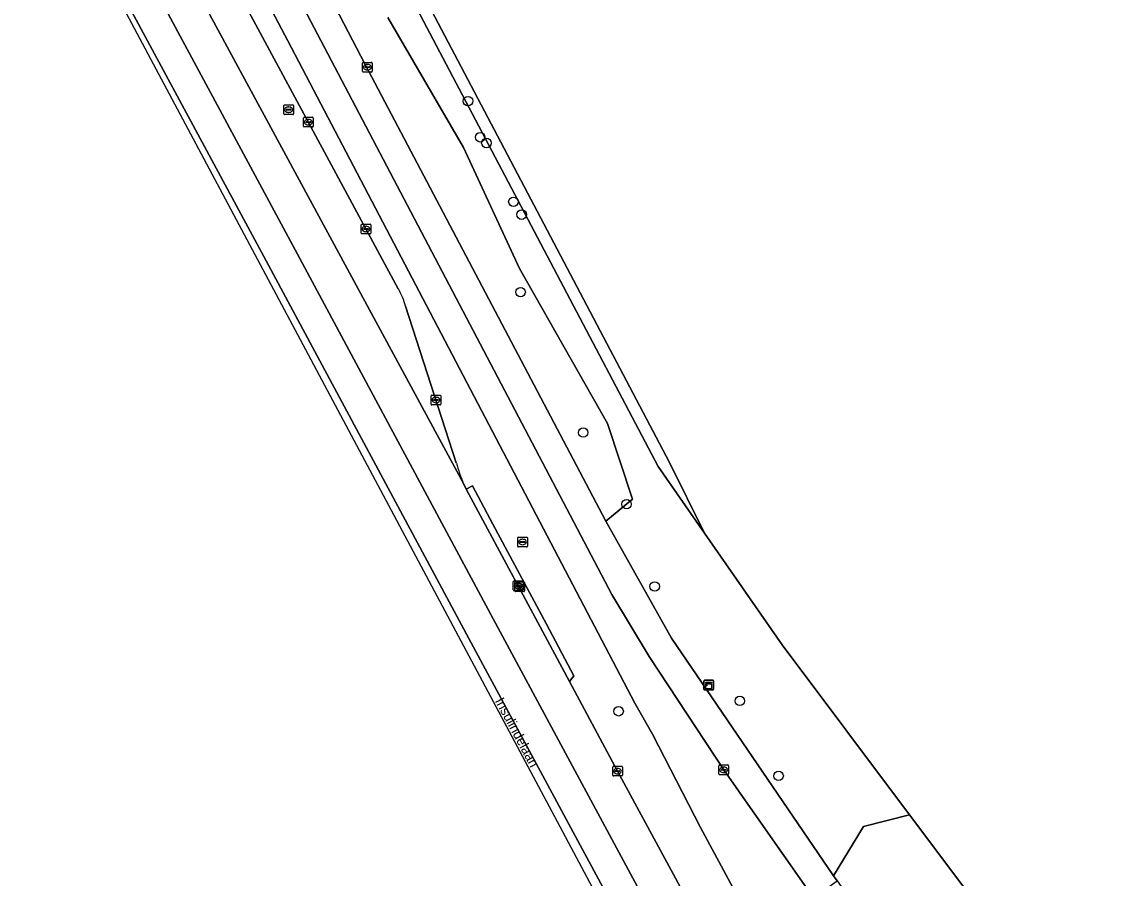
# Model space of a CAD drawing. Extents: x 162417 to 163722, y 384268 to 385417.
# Drawn here: x 162734.5 to 162846, y 384388.4 to 384476.6 of the extents above; entities that cross this region are included whole.
import ezdxf

# ---------------------------------------------------------------- set-up
doc = ezdxf.new("R2010")
doc.units = 0
for name, color, linetype in [('IMGEO_Berm_groen', 7, 'Continuous'), ('IMGEO_Boom', 7, 'Continuous'), ('IMGEO_Fietspad_open', 7, 'Continuous'), ('IMGEO_Groenvoorziening', 7, 'Continuous'), ('IMGEO_Kast', 7, 'Continuous'), ('IMGEO_Kolk', 7, 'Continuous'), ('IMGEO_Meer_plas_ven_vijver', 7, 'Continuous'), ('IMGEO_Openbare_ruimte_label', 7, 'Continuous'), ('IMGEO_Rijbaan_regionaal_gesloten', 7, 'Continuous'), ('IMGEO_Rioolput', 7, 'Continuous'), ('IMGEO_Terreindeel_open', 7, 'Continuous'), ('IMGEO_Voetpad_open', 7, 'Continuous')]:
    doc.layers.add(name, color=color, linetype=linetype)

msp = doc.modelspace()

# ---------------------------------------------------------------- linework, layer by layer
at = {"layer": 'IMGEO_Berm_groen'}
for points in [[(162754.27, 384502.15), (162755.39, 384500), (162769.87, 384472.16), (162794.62, 384425.16), (162797.36, 384427.41), (162794.8, 384435.21), (162785.75, 384451.17), (162779.97, 384463.61), (162772.19, 384477)], [(162816.42, 384372.9), (162812.18, 384379.37), (162810.21, 384382.67), (162810.08, 384382.89), (162808.48, 384386.03), (162807.93, 384387.03), (162804.38, 384393.64), (162799.42, 384403.24), (162797.61, 384406.44), (162761.9, 384474.57), (162755.43, 384486.9), (162751.85, 384493.51), (162748.56, 384499.79)], [(162746.31, 384499.11), (162773.28, 384449.07)], [(162774.01, 384447.28), (162779.24, 384431.15)], [(162779.97, 384429.02), (162780.27, 384428.44), (162780.92, 384428.78), (162782.99, 384424.84), (162788.51, 384414.57), (162791.34, 384409.23), (162791.24, 384409.1), (162790.89, 384408.66), (162795.83, 384399.44), (162823.04, 384349.18), (162830.65, 384335.7), (162839.9, 384319.71)]]:
    msp.add_lwpolyline(points, dxfattribs=at)
for centre, radius, start, end in [((162766.73, 384445.34), 7.54, 14.8426, 29.5957), ((162795.8, 384435.6), 17.14, 195.0738, 202.5866)]:
    msp.add_arc(centre, radius, start, end, dxfattribs=at)
at = {"layer": 'IMGEO_Boom'}
for centre in [(162780.45, 384468.38), (162781.7, 384464.66), (162782.34, 384464.07), (162785.12, 384458.02), (162785.97, 384456.7), (162785.86, 384448.73), (162792.3, 384434.28), (162796.76, 384426.91), (162799.65, 384418.44), (162808.41, 384406.67), (162795.94, 384405.6), (162812.4, 384398.95)]:
    msp.add_circle(centre, 0.489, dxfattribs=at)
at = {"layer": 'IMGEO_Fietspad_open'}
msp.add_lwpolyline([(162764.98, 384475.28), (162757.93, 384488.68), (162752.8, 384498.47), (162752.11, 384500), (162748.56, 384499.79), (162751.85, 384493.51), (162755.43, 384486.9), (162761.9, 384474.57), (162797.61, 384406.44), (162799.42, 384403.24), (162804.38, 384393.64), (162807.93, 384387.03), (162808.48, 384386.03), (162810.08, 384382.89), (162810.21, 384382.67), (162813.11, 384384.55), (162816, 384386.42), (162806.83, 384399.46), (162799.07, 384411.25), (162795.23, 384417.63)], close=True, dxfattribs=at)
at = {"layer": 'IMGEO_Groenvoorziening'}
for points in [[(162767.81, 384491.93), (162800.01, 384430.78), (162804.77, 384423.92), (162801.16, 384431.19), (162768.87, 384492.59)], [(162772.19, 384477), (162779.97, 384463.61), (162785.75, 384451.17), (162794.8, 384435.21), (162797.36, 384427.41), (162794.62, 384425.16), (162801.38, 384413.11), (162818.05, 384388.68), (162821.14, 384393.75), (162825.87, 384394.96), (162812.76, 384412.45), (162804.77, 384423.92), (162800.01, 384430.78), (162767.81, 384491.93)], [(162847.62, 384365.96), (162825.87, 384394.96), (162821.14, 384393.75), (162818.05, 384388.68), (162818.43, 384388.14), (162860.16, 384329.06)]]:
    msp.add_lwpolyline(points, dxfattribs=at)
at = {"layer": 'IMGEO_Kast'}
for p, q in [((162804.72, 384407.87), (162804.72, 384408.71)), ((162804.72, 384408.71), (162804.72, 384407.87)), ((162804.79, 384408.79), (162805.63, 384408.79)), ((162805.63, 384408.79), (162804.79, 384408.79)), ((162805.71, 384408.72), (162805.71, 384407.88)), ((162805.71, 384407.88), (162805.71, 384408.72)), ((162805.64, 384407.79), (162804.8, 384407.79)), ((162804.8, 384407.79), (162805.64, 384407.79))]:
    msp.add_line(p, q, dxfattribs=at)
for points in [[(162804.91, 384408.58), (162805.51, 384408.58), (162805.51, 384408.5), (162804.91, 384408.5), (162804.91, 384408.58)], [(162804.91, 384408.41), (162805.51, 384408.41), (162805.51, 384407.92), (162804.91, 384407.92), (162804.91, 384408.41)]]:
    msp.add_lwpolyline(points, dxfattribs=at)
msp.add_circle((162804.99, 384408.26), 0.0377, dxfattribs=at)
for centre, start, end in [((162804.79, 384408.71), 92.4484, 184.2845), ((162804.79, 384408.71), 92.4484, 184.2845), ((162805.64, 384408.71), 2.4484, 94.2845), ((162805.64, 384408.71), 2.4484, 94.2845), ((162804.79, 384407.87), 182.4484, 274.2845), ((162804.79, 384407.87), 182.4484, 274.2845), ((162805.64, 384407.87), 272.4484, 4.2845), ((162805.64, 384407.87), 272.4484, 4.2845)]:
    msp.add_arc(centre, 0.0779, start, end, dxfattribs=at)
at = {"layer": 'IMGEO_Kolk'}
for p, q in [((162763.53, 384465.79), (162763.53, 384466.64)), ((162763.6, 384466.72), (162764.45, 384466.72)), ((162763.79, 384466.21), (162763.79, 384466.22)), ((162763.83, 384466.26), (162764.23, 384466.26)), ((162764.22, 384466.17), (162763.83, 384466.17)), ((162764.02, 384466.5), (162764.04, 384466.5)), ((162764.27, 384466.22), (162764.27, 384466.21)), ((162764.53, 384466.64), (162764.53, 384465.79)), ((162764.45, 384465.72), (162763.6, 384465.72)), ((162764.04, 384465.94), (162764.01, 384465.94)), ((162769.46, 384454.79), (162769.46, 384455.65)), ((162769.54, 384455.72), (162770.39, 384455.72)), ((162769.72, 384455.21), (162769.72, 384455.23)), ((162769.76, 384455.26), (162770.16, 384455.26)), ((162770.16, 384455.18), (162769.76, 384455.18)), ((162769.95, 384455.5), (162769.98, 384455.5)), ((162769.97, 384454.94), (162769.95, 384454.94)), ((162770.21, 384455.23), (162770.21, 384455.21)), ((162770.46, 384455.65), (162770.46, 384454.79)), ((162770.39, 384454.72), (162769.54, 384454.72)), ((162776.65, 384437.2), (162776.65, 384438.06)), ((162776.72, 384438.13), (162777.58, 384438.13)), ((162777.58, 384437.13), (162776.72, 384437.13)), ((162776.91, 384437.62), (162776.91, 384437.64)), ((162776.95, 384437.67), (162777.35, 384437.67)), ((162777.34, 384437.59), (162776.95, 384437.59)), ((162777.16, 384437.35), (162777.13, 384437.35)), ((162777.14, 384437.91), (162777.16, 384437.91)), ((162777.39, 384437.64), (162777.39, 384437.62)), ((162777.65, 384438.06), (162777.65, 384437.2)), ((162785.11, 384418.08), (162785.11, 384418.94)), ((162785.19, 384419.01), (162786.04, 384419.01)), ((162785.27, 384417.99), (162785.27, 384418.85)), ((162785.34, 384418.92), (162786.19, 384418.92)), ((162785.37, 384418.5), (162785.37, 384418.52)), ((162785.81, 384418.47), (162785.41, 384418.47)), ((162785.42, 384418.55), (162785.81, 384418.55)), ((162785.52, 384418.41), (162785.52, 384418.43)), ((162785.96, 384418.38), (162785.56, 384418.38)), ((162785.57, 384418.46), (162785.96, 384418.46)), ((162785.6, 384418.79), (162785.63, 384418.79)), ((162785.62, 384418.23), (162785.6, 384418.23)), ((162785.75, 384418.7), (162785.78, 384418.7)), ((162785.78, 384418.14), (162785.75, 384418.14)), ((162785.86, 384418.52), (162785.86, 384418.5)), ((162786.01, 384418.43), (162786.01, 384418.41)), ((162786.11, 384418.94), (162786.11, 384418.08)), ((162786.27, 384418.85), (162786.27, 384417.99)), ((162786.04, 384418.01), (162785.19, 384418.01)), ((162786.19, 384417.92), (162785.34, 384417.92)), ((162795.33, 384399.01), (162795.33, 384399.86)), ((162795.41, 384399.94), (162796.26, 384399.94)), ((162795.59, 384399.43), (162795.59, 384399.44)), ((162796.03, 384399.39), (162795.63, 384399.39)), ((162795.64, 384399.48), (162796.03, 384399.48)), ((162795.82, 384399.72), (162795.85, 384399.72)), ((162796.08, 384399.44), (162796.08, 384399.43)), ((162796.33, 384399.86), (162796.33, 384399.01)), ((162806.26, 384399.15), (162806.26, 384400)), ((162806.33, 384400.08), (162807.18, 384400.08)), ((162806.52, 384399.57), (162806.52, 384399.58)), ((162806.56, 384399.62), (162806.96, 384399.62)), ((162806.95, 384399.53), (162806.56, 384399.53)), ((162806.77, 384399.3), (162806.74, 384399.3)), ((162806.75, 384399.85), (162806.77, 384399.85)), ((162807, 384399.58), (162807, 384399.57)), ((162807.26, 384400), (162807.26, 384399.15)), ((162796.26, 384398.94), (162795.41, 384398.94)), ((162795.84, 384399.16), (162795.82, 384399.16)), ((162807.18, 384399.07), (162806.33, 384399.07))]:
    msp.add_line(p, q, dxfattribs=at)
for points in [[(162763.53, 384465.79), (162763.53, 384466.64)], [(162763.6, 384466.72), (162764.45, 384466.72)], [(162764.53, 384466.64), (162764.53, 384465.79)], [(162764.45, 384465.72), (162763.6, 384465.72)], [(162769.46, 384454.79), (162769.46, 384455.65)], [(162769.54, 384455.72), (162770.39, 384455.72)], [(162770.46, 384455.65), (162770.46, 384454.79)], [(162770.39, 384454.72), (162769.54, 384454.72)], [(162776.65, 384437.2), (162776.65, 384438.06)], [(162776.72, 384438.13), (162777.58, 384438.13)], [(162777.58, 384437.13), (162776.72, 384437.13)], [(162777.65, 384438.06), (162777.65, 384437.2)], [(162785.11, 384418.08), (162785.11, 384418.94)], [(162785.19, 384419.01), (162786.04, 384419.01)], [(162785.27, 384417.99), (162785.27, 384418.85)], [(162785.34, 384418.92), (162786.19, 384418.92)], [(162786.11, 384418.94), (162786.11, 384418.08)], [(162786.27, 384418.85), (162786.27, 384417.99)], [(162786.04, 384418.01), (162785.19, 384418.01)], [(162786.19, 384417.92), (162785.34, 384417.92)], [(162795.33, 384399.01), (162795.33, 384399.86)], [(162795.41, 384399.94), (162796.26, 384399.94)], [(162796.33, 384399.86), (162796.33, 384399.01)], [(162806.26, 384399.15), (162806.26, 384400)], [(162806.33, 384400.08), (162807.18, 384400.08)], [(162807.26, 384400), (162807.26, 384399.15)], [(162796.26, 384398.94), (162795.41, 384398.94)], [(162807.18, 384399.07), (162806.33, 384399.07)]]:
    msp.add_lwpolyline(points, dxfattribs=at)
for centre, radius, start, end in [((162763.6, 384466.64), 0.0765, 91.552, 178.448), ((162763.6, 384466.64), 0.0765, 91.552, 178.448), ((162763.83, 384466.22), 0.0403, 85.8775, 175.7526), ((162763.82, 384466.21), 0.0366, 178.938, 274.7102), ((162764.23, 384466.22), 0.043, 264.8664, 352.4533), ((162764.23, 384466.22), 0.0386, 1.7309, 96.639), ((162764.45, 384466.64), 0.0765, 1.552, 88.448), ((162764.45, 384466.64), 0.0765, 1.552, 88.448), ((162763.6, 384465.79), 0.0765, 181.552, 268.448), ((162763.6, 384465.79), 0.0765, 181.552, 268.448), ((162764.45, 384465.79), 0.0765, 271.552, 358.448), ((162764.45, 384465.79), 0.0765, 271.552, 358.448), ((162769.54, 384455.64), 0.0765, 91.552, 178.448), ((162769.54, 384455.64), 0.0765, 91.552, 178.448), ((162769.76, 384455.22), 0.0403, 85.8775, 175.7526), ((162769.76, 384455.21), 0.0366, 178.938, 274.7102), ((162770.17, 384455.22), 0.0386, 1.7309, 96.639), ((162770.16, 384455.22), 0.043, 264.8664, 352.4533), ((162770.39, 384455.64), 0.0765, 1.552, 88.448), ((162770.39, 384455.64), 0.0765, 1.552, 88.448), ((162769.54, 384454.8), 0.0765, 181.552, 268.448), ((162769.54, 384454.8), 0.0765, 181.552, 268.448), ((162770.39, 384454.8), 0.0765, 271.552, 358.448), ((162770.39, 384454.8), 0.0765, 271.552, 358.448), ((162776.72, 384438.05), 0.0765, 91.552, 178.448), ((162776.72, 384438.05), 0.0765, 91.552, 178.448), ((162776.72, 384437.2), 0.0765, 181.552, 268.448), ((162776.72, 384437.2), 0.0765, 181.552, 268.448), ((162776.95, 384437.63), 0.0403, 85.8775, 175.7526), ((162776.94, 384437.62), 0.0366, 178.938, 274.7102), ((162777.35, 384437.63), 0.043, 264.8664, 352.4533), ((162777.35, 384437.63), 0.0386, 1.7309, 96.639), ((162777.57, 384438.05), 0.0765, 1.552, 88.448), ((162777.57, 384438.05), 0.0765, 1.552, 88.448), ((162777.57, 384437.2), 0.0765, 271.552, 358.448), ((162777.57, 384437.2), 0.0765, 271.552, 358.448), ((162785.19, 384418.93), 0.0765, 91.552, 178.448), ((162785.19, 384418.93), 0.0765, 91.552, 178.448), ((162785.34, 384418.84), 0.0765, 91.552, 178.448), ((162785.34, 384418.84), 0.0765, 91.552, 178.448), ((162785.41, 384418.51), 0.0403, 85.8775, 175.7526), ((162785.41, 384418.5), 0.0366, 178.938, 274.7102), ((162785.56, 384418.42), 0.0403, 85.8775, 175.7526), ((162785.56, 384418.41), 0.0366, 178.938, 274.7102), ((162785.82, 384418.51), 0.0386, 1.7309, 96.639), ((162785.81, 384418.51), 0.043, 264.8664, 352.4533), ((162785.97, 384418.42), 0.0386, 1.7309, 96.639), ((162785.97, 384418.42), 0.043, 264.8664, 352.4533), ((162786.04, 384418.93), 0.0765, 1.552, 88.448), ((162786.04, 384418.93), 0.0765, 1.552, 88.448), ((162786.19, 384418.84), 0.0765, 1.552, 88.448), ((162786.19, 384418.84), 0.0765, 1.552, 88.448), ((162785.19, 384418.09), 0.0765, 181.552, 268.448), ((162785.19, 384418.09), 0.0765, 181.552, 268.448), ((162785.34, 384417.99), 0.0765, 181.552, 268.448), ((162785.34, 384417.99), 0.0765, 181.552, 268.448), ((162786.04, 384418.09), 0.0765, 271.552, 358.448), ((162786.04, 384418.09), 0.0765, 271.552, 358.448), ((162786.19, 384417.99), 0.0765, 271.552, 358.448), ((162786.19, 384417.99), 0.0765, 271.552, 358.448), ((162795.41, 384399.86), 0.0765, 91.552, 178.448), ((162795.41, 384399.86), 0.0765, 91.552, 178.448), ((162795.63, 384399.44), 0.0403, 85.8775, 175.7526), ((162795.63, 384399.43), 0.0366, 178.938, 274.7102), ((162796.04, 384399.44), 0.0386, 1.7309, 96.639), ((162796.03, 384399.44), 0.043, 264.8664, 352.4533), ((162796.26, 384399.86), 0.0765, 1.552, 88.448), ((162796.26, 384399.86), 0.0765, 1.552, 88.448), ((162806.33, 384400), 0.0765, 91.552, 178.448), ((162806.33, 384400), 0.0765, 91.552, 178.448), ((162806.56, 384399.58), 0.0403, 85.8775, 175.7526), ((162806.55, 384399.57), 0.0366, 178.938, 274.7102), ((162806.96, 384399.57), 0.043, 264.8664, 352.4533), ((162806.96, 384399.58), 0.0386, 1.7309, 96.639), ((162807.18, 384400), 0.0765, 1.552, 88.448), ((162807.18, 384400), 0.0765, 1.552, 88.448), ((162795.41, 384399.01), 0.0765, 181.552, 268.448), ((162795.41, 384399.01), 0.0765, 181.552, 268.448), ((162796.26, 384399.01), 0.0765, 271.552, 358.448), ((162796.26, 384399.01), 0.0765, 271.552, 358.448), ((162806.33, 384399.15), 0.0765, 181.552, 268.448), ((162806.33, 384399.15), 0.0765, 181.552, 268.448), ((162807.18, 384399.15), 0.0765, 271.552, 358.448), ((162807.18, 384399.15), 0.0765, 271.552, 358.448)]:
    msp.add_arc(centre, radius, start, end, dxfattribs=at)
for centre, major_axis, ratio, start_param, end_param in [((162764.01, 384466.22), (-0.387, 0.002), 0.722429, 4.712389, 7.853982), ((162764.04, 384466.22), (-0.39, 0.002), 0.717154, 1.570796, 4.712389), ((162769.95, 384455.22), (-0.387, 0.002), 0.722429, 4.712389, 7.853982), ((162769.97, 384455.22), (-0.39, 0.002), 0.717154, 1.570796, 4.712389), ((162777.14, 384437.63), (-0.387, 0.002), 0.722429, 4.712389, 7.853982), ((162777.16, 384437.63), (-0.39, 0.002), 0.717154, 1.570796, 4.712389), ((162785.6, 384418.51), (-0.387, 0.002), 0.722429, 4.712389, 7.853982), ((162785.75, 384418.42), (-0.387, 0.002), 0.722429, 4.712389, 7.853982), ((162785.62, 384418.51), (-0.39, 0.002), 0.717154, 1.570796, 4.712389), ((162785.78, 384418.42), (-0.39, 0.002), 0.717154, 1.570796, 4.712389), ((162795.82, 384399.44), (-0.387, 0.002), 0.722429, 4.712389, 7.853982), ((162795.84, 384399.44), (-0.39, 0.002), 0.717154, 1.570796, 4.712389), ((162806.74, 384399.57), (-0.387, 0.002), 0.722429, 4.712389, 7.853982), ((162806.77, 384399.57), (-0.39, 0.002), 0.717154, 1.570796, 4.712389)]:
    msp.add_ellipse(centre, major_axis=major_axis, ratio=ratio, start_param=start_param, end_param=end_param, dxfattribs=at)
at = {"layer": 'IMGEO_Meer_plas_ven_vijver'}
msp.add_lwpolyline([(162768.87, 384492.59), (162801.16, 384431.19), (162804.77, 384423.92), (162812.76, 384412.45), (162825.87, 384394.96), (162847.62, 384365.96), (162858.02, 384352.1), (162869.39, 384336.93), (162873.92, 384331.77), (162873.94, 384331.75), (162880.68, 384326.96), (162888.3, 384324.02), (162890.62, 384323.75), (162895.67, 384323.18), (162904.39, 384324.1), (162927.53, 384330.45), (162944.64, 384335.14), (162971.11, 384342.4), (162976.25, 384406.67), (162962.24, 384407.64), (162968.83, 384503.48)], dxfattribs=at)
at = {"layer": 'IMGEO_Rijbaan_regionaal_gesloten'}
for points in [[(162742.36, 384498.6), (162742.11, 384498.57), (162738.46, 384498.1), (162742.85, 384489.94), (162762.9, 384452.62), (162783.02, 384415.1), (162802.43, 384379.07), (162810.84, 384363.47), (162822.01, 384342.68), (162828.12, 384331.64), (162832.26, 384324.52), (162835.94, 384318.64), (162840.23, 384312.43), (162842.77, 384309.11), (162846.14, 384305.7), (162857.34, 384295.59), (162861.95, 384291.57), (162872.15, 384283.83)], [(162746.31, 384499.11), (162742.59, 384498.63), (162742.36, 384498.6), (162779.97, 384429.02)], [(162839.9, 384319.71), (162830.65, 384335.7), (162823.04, 384349.18), (162795.83, 384399.44), (162790.89, 384408.66), (162786.13, 384417.55), (162780.27, 384428.44), (162779.97, 384429.02), (162742.36, 384498.6)], [(162773.28, 384449.07), (162746.31, 384499.11)], [(162734.54, 384497.59), (162794.86, 384384.42), (162830.58, 384316.87), (162838.99, 384308.46), (162838.41, 384309.08), (162835.68, 384312.55), (162832.33, 384317.3), (162828.35, 384324.29), (162825.26, 384329.91), (162819.13, 384341.17), (162808.47, 384361.16), (162799.61, 384377.69), (162780.52, 384413.08), (162759.93, 384451.49), (162740.22, 384488.09), (162734.96, 384497.64), (162734.54, 384497.59)], [(162846.14, 384305.7), (162842.77, 384309.11), (162840.23, 384312.43), (162835.94, 384318.64), (162832.26, 384324.52), (162828.12, 384331.64), (162822.01, 384342.68), (162810.84, 384363.47), (162802.43, 384379.07), (162783.02, 384415.1), (162762.9, 384452.62), (162742.85, 384489.94)], [(162740.22, 384488.09), (162759.93, 384451.49), (162780.52, 384413.08), (162799.61, 384377.69), (162808.47, 384361.16), (162819.13, 384341.17), (162825.26, 384329.91), (162828.35, 384324.29), (162832.33, 384317.3), (162835.68, 384312.55), (162838.41, 384309.08), (162838.99, 384308.46), (162849.39, 384298.06)], [(162779.24, 384431.15), (162774.01, 384447.28)]]:
    msp.add_lwpolyline(points, dxfattribs=at)
for centre, radius, start, end in [((162766.73, 384445.34), 7.54, 14.8426, 29.5957), ((162795.8, 384435.6), 17.14, 195.0738, 202.5866)]:
    msp.add_arc(centre, radius, start, end, dxfattribs=at)
at = {"layer": 'IMGEO_Rioolput'}
for p, q in [((162769.59, 384471.45), (162769.59, 384472.3)), ((162769.67, 384472.37), (162770.52, 384472.37)), ((162769.85, 384471.87), (162769.85, 384471.88)), ((162770.29, 384471.83), (162769.89, 384471.83)), ((162769.9, 384471.92), (162770.29, 384471.92)), ((162770.08, 384472.15), (162770.11, 384472.15)), ((162770.34, 384471.88), (162770.34, 384471.87)), ((162770.6, 384472.3), (162770.6, 384471.45)), ((162770.52, 384471.37), (162769.67, 384471.37)), ((162770.1, 384471.59), (162770.08, 384471.59)), ((162761.5, 384467.07), (162761.5, 384467.92)), ((162761.58, 384468), (162762.43, 384468)), ((162761.76, 384467.49), (162761.76, 384467.5)), ((162762.2, 384467.45), (162761.8, 384467.45)), ((162761.81, 384467.54), (162762.2, 384467.54)), ((162761.99, 384467.78), (162762.02, 384467.78)), ((162762.01, 384467.22), (162761.99, 384467.22)), ((162762.25, 384467.5), (162762.25, 384467.49)), ((162762.51, 384467.92), (162762.51, 384467.07)), ((162762.43, 384467), (162761.58, 384467)), ((162785.56, 384422.59), (162785.56, 384423.44)), ((162785.63, 384423.52), (162786.49, 384423.52)), ((162785.82, 384423.01), (162785.82, 384423.02)), ((162785.86, 384423.06), (162786.26, 384423.06)), ((162786.25, 384422.97), (162785.86, 384422.97)), ((162786.07, 384422.74), (162786.04, 384422.74)), ((162786.05, 384423.3), (162786.07, 384423.3)), ((162786.3, 384423.02), (162786.3, 384423.01)), ((162786.56, 384423.44), (162786.56, 384422.59)), ((162786.49, 384422.52), (162785.63, 384422.52))]:
    msp.add_line(p, q, dxfattribs=at)
for points in [[(162769.59, 384471.45), (162769.59, 384472.3)], [(162769.67, 384472.37), (162770.52, 384472.37)], [(162770.6, 384472.3), (162770.6, 384471.45)], [(162770.52, 384471.37), (162769.67, 384471.37)], [(162761.5, 384467.07), (162761.5, 384467.92)], [(162761.58, 384468), (162762.43, 384468)], [(162762.51, 384467.92), (162762.51, 384467.07)], [(162762.43, 384467), (162761.58, 384467)], [(162785.56, 384422.59), (162785.56, 384423.44)], [(162785.63, 384423.52), (162786.49, 384423.52)], [(162786.56, 384423.44), (162786.56, 384422.59)], [(162786.49, 384422.52), (162785.63, 384422.52)]]:
    msp.add_lwpolyline(points, dxfattribs=at)
for centre, radius, start, end in [((162769.67, 384472.3), 0.0765, 91.552, 178.448), ((162769.67, 384472.3), 0.0765, 91.552, 178.448), ((162769.89, 384471.88), 0.0403, 85.8775, 175.7526), ((162769.89, 384471.87), 0.0366, 178.938, 274.7102), ((162770.3, 384471.88), 0.0386, 1.7309, 96.639), ((162770.29, 384471.87), 0.043, 264.8664, 352.4533), ((162770.52, 384472.3), 0.0765, 1.552, 88.448), ((162770.52, 384472.3), 0.0765, 1.552, 88.448), ((162769.67, 384471.45), 0.0765, 181.552, 268.448), ((162769.67, 384471.45), 0.0765, 181.552, 268.448), ((162770.52, 384471.45), 0.0765, 271.552, 358.448), ((162770.52, 384471.45), 0.0765, 271.552, 358.448), ((162761.58, 384467.92), 0.0765, 91.552, 178.448), ((162761.58, 384467.92), 0.0765, 91.552, 178.448), ((162761.8, 384467.5), 0.0403, 85.8775, 175.7526), ((162761.8, 384467.49), 0.0366, 178.938, 274.7102), ((162762.21, 384467.5), 0.0386, 1.7309, 96.639), ((162762.2, 384467.5), 0.043, 264.8664, 352.4533), ((162762.43, 384467.92), 0.0765, 1.552, 88.448), ((162762.43, 384467.92), 0.0765, 1.552, 88.448), ((162761.58, 384467.07), 0.0765, 181.552, 268.448), ((162761.58, 384467.07), 0.0765, 181.552, 268.448), ((162762.43, 384467.07), 0.0765, 271.552, 358.448), ((162762.43, 384467.07), 0.0765, 271.552, 358.448), ((162785.63, 384423.44), 0.0765, 91.552, 178.448), ((162785.63, 384423.44), 0.0765, 91.552, 178.448), ((162785.63, 384422.59), 0.0765, 181.552, 268.448), ((162785.63, 384422.59), 0.0765, 181.552, 268.448), ((162785.86, 384423.02), 0.0403, 85.8775, 175.7526), ((162785.85, 384423.01), 0.0366, 178.938, 274.7102), ((162786.26, 384423.02), 0.043, 264.8664, 352.4533), ((162786.26, 384423.02), 0.0386, 1.7309, 96.639), ((162786.48, 384423.44), 0.0765, 1.552, 88.448), ((162786.48, 384423.44), 0.0765, 1.552, 88.448), ((162786.48, 384422.59), 0.0765, 271.552, 358.448), ((162786.48, 384422.59), 0.0765, 271.552, 358.448)]:
    msp.add_arc(centre, radius, start, end, dxfattribs=at)
for centre, major_axis, ratio, start_param, end_param in [((162770.08, 384471.87), (-0.387, 0.002), 0.722429, 4.712389, 7.853982), ((162770.11, 384471.87), (-0.39, 0.002), 0.717154, 1.570796, 4.712389), ((162761.99, 384467.5), (-0.387, 0.002), 0.722429, 4.712389, 7.853982), ((162762.02, 384467.5), (-0.39, 0.002), 0.717154, 1.570796, 4.712389), ((162786.05, 384423.02), (-0.387, 0.002), 0.722429, 4.712389, 7.853982), ((162786.07, 384423.02), (-0.39, 0.002), 0.717154, 1.570796, 4.712389)]:
    msp.add_ellipse(centre, major_axis=major_axis, ratio=ratio, start_param=start_param, end_param=end_param, dxfattribs=at)
at = {"layer": 'IMGEO_Terreindeel_open'}
msp.add_lwpolyline([(162780.27, 384428.44), (162786.13, 384417.55), (162790.89, 384408.66), (162791.24, 384409.1), (162791.34, 384409.23), (162788.51, 384414.57), (162782.99, 384424.84), (162780.92, 384428.78)], close=True, dxfattribs=at)
at = {"layer": 'IMGEO_Voetpad_open'}
msp.add_lwpolyline([(162752.11, 384500), (162752.8, 384498.47), (162757.93, 384488.68), (162764.98, 384475.28), (162795.23, 384417.63), (162799.07, 384411.25), (162806.83, 384399.46), (162816, 384386.42), (162818.43, 384388.14), (162818.05, 384388.68), (162801.38, 384413.11), (162794.62, 384425.16), (162769.87, 384472.16), (162755.39, 384500)], dxfattribs=at)

# ---------------------------------------------------------------- texts
at = {"layer": 'IMGEO_Openbare_ruimte_label'}
msp.add_text('Insulindelaan', height=1, rotation=298.1533, dxfattribs=at).set_placement((162783.19, 384406.67))

doc.saveas('drawing.dxf')
